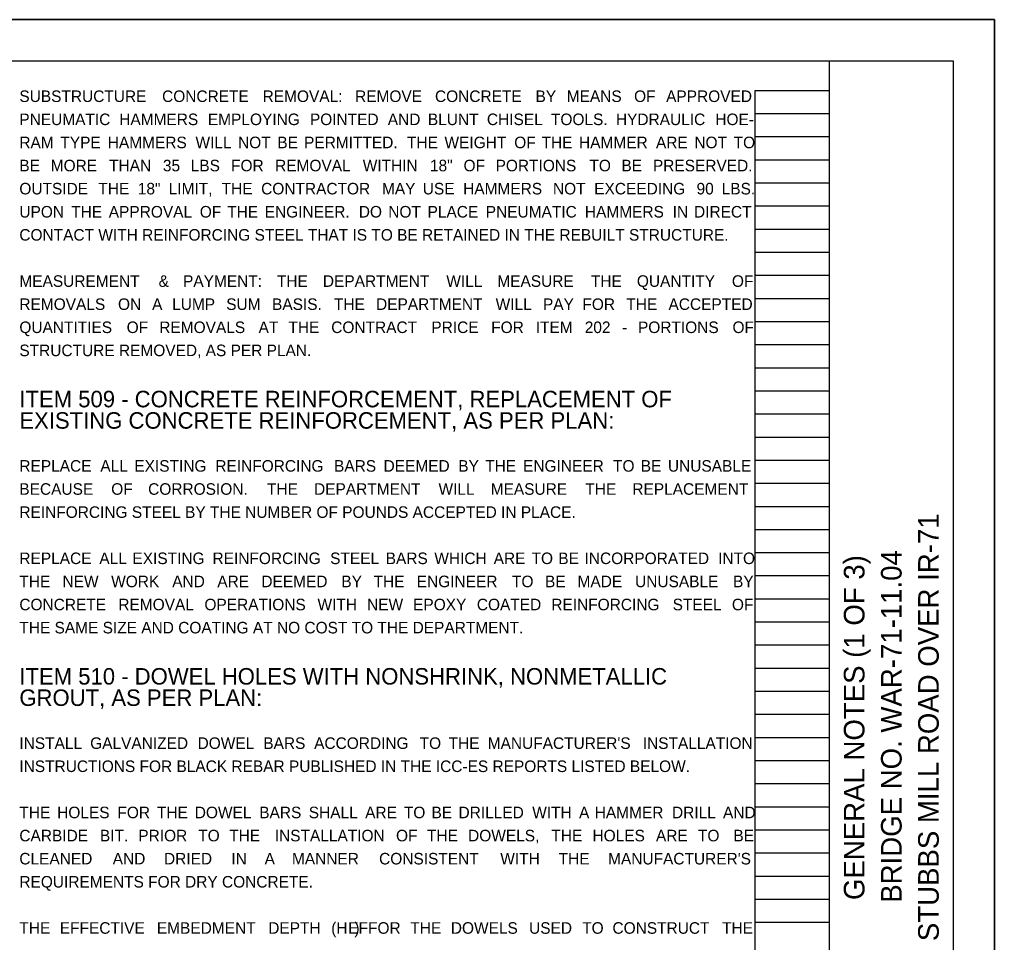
# Model space of a CAD drawing. Extents: x 0 to 34, y 0 to 22.
# Drawn here: x 22.19 to 34, y 10.81 to 22 of the extents above; entities that cross this region are included whole.
import ezdxf

# ---------------------------------------------------------------- set-up
doc = ezdxf.new("R2010")
doc.units = 0
for name, color, linetype in [('BR_P_Gen_Text', 7, 'Continuous'), ('SC_Scratch1', 7, 'Continuous'), ('SH_Border', 7, 'Continuous'), ('SH_Cut_Line', 7, 'Continuous'), ('SH_Data', 7, 'Continuous'), ('SH_Text', 7, 'Continuous')]:
    doc.layers.add(name, color=color, linetype=linetype)

msp = doc.modelspace()

# ---------------------------------------------------------------- linework, layer by layer
at = {"layer": 'SC_Scratch1'}
for p, q in [((31.1, 0.98), (31.1, 21.14)), ((31.1, 21.14), (32, 21.14)), ((32, 0.98), (32, 21.14)), ((31.1, 20.86), (32, 20.86)), ((31.1, 20.58), (32, 20.58)), ((31.1, 20.3), (32, 20.3)), ((31.1, 20.02), (32, 20.02)), ((31.1, 19.74), (32, 19.74)), ((31.1, 19.46), (32, 19.46)), ((31.1, 19.18), (32, 19.18)), ((31.1, 18.9), (32, 18.9)), ((31.1, 18.62), (32, 18.62)), ((31.1, 18.34), (32, 18.34)), ((31.1, 18.06), (32, 18.06)), ((31.1, 17.78), (32, 17.78)), ((31.1, 17.5), (32, 17.5)), ((31.1, 17.22), (32, 17.22)), ((31.1, 16.94), (32, 16.94)), ((31.1, 16.66), (32, 16.66)), ((31.1, 16.38), (32, 16.38)), ((31.1, 16.1), (32, 16.1)), ((31.1, 15.82), (32, 15.82)), ((31.1, 15.54), (32, 15.54)), ((31.1, 15.26), (32, 15.26)), ((31.1, 14.98), (32, 14.98)), ((31.1, 14.7), (32, 14.7)), ((31.1, 14.42), (32, 14.42)), ((31.1, 14.14), (32, 14.14)), ((31.1, 13.86), (32, 13.86)), ((31.1, 13.58), (32, 13.58)), ((31.1, 13.3), (32, 13.3)), ((31.1, 13.02), (32, 13.02)), ((31.1, 12.74), (32, 12.74)), ((31.1, 12.46), (32, 12.46)), ((31.1, 12.18), (32, 12.18)), ((31.1, 11.9), (32, 11.9)), ((31.1, 11.62), (32, 11.62)), ((31.1, 11.34), (32, 11.34)), ((31.1, 11.06), (32, 11.06))]:
    msp.add_line(p, q, dxfattribs=at)
msp.add_lwpolyline([(0, 22), (34, 22), (34, 0), (0, 0)], close=True, dxfattribs=at)
at = {"layer": 'SH_Border'}
msp.add_line((32, 0.5), (32, 21.5), dxfattribs=at)
msp.add_lwpolyline([(1.5, 21.5), (33.5, 21.5), (33.5, 0.5), (1.5, 0.5)], close=True, dxfattribs=at)
at = {"layer": 'SH_Cut_Line'}
msp.add_lwpolyline([(0, 0), (34, 0), (34, 22), (0, 22)], close=True, dxfattribs=at)

# ---------------------------------------------------------------- texts
at = {"layer": 'BR_P_Gen_Text'}
for s, p in [('ITEM 509 - CONCRETE REINFORCEMENT, REPLACEMENT OF ', (22.187, 17.3)), ('EXISTING CONCRETE REINFORCEMENT, AS PER PLAN: ', (22.187, 17.041)), ('ITEM 510 - DOWEL HOLES WITH NONSHRINK, NONMETALLIC ', (22.187, 13.94)), ('GROUT, AS PER PLAN:', (22.187, 13.681))]:
    msp.add_text(s, height=0.2, dxfattribs=at).set_placement(p)
at = {"layer": 'SH_Data'}
for s, p in [('STUBBS MILL ROAD OVER IR-71', (33.325, 10.831)), ('GENERAL NOTES (1 OF 3)', (32.425, 11.329)), ('BRIDGE NO. WAR-71-11.04', (32.875, 11.296))]:
    msp.add_text(s, height=0.25, rotation=90, dxfattribs=at).set_placement(p)
at = {"layer": 'SH_Text'}
for s, p in [('SUBSTRUCTURE ', (22.187, 21)), ('CONCRETE ', (23.916, 21)), ('REMOVAL: ', (25.134, 21)), ('REMOVE ', (26.254, 21)), ('CONCRETE ', (27.222, 21)), ('BY ', (28.44, 21)), ('MEANS ', (28.818, 21)), ('OF ', (29.634, 21)), ('APPROVED ', (30.022, 21)), ('PNEUMATIC ', (22.187, 20.72)), ('HAMMERS ', (23.397, 20.72)), ('EMPLOYING ', (24.471, 20.72)), ('POINTED ', (25.707, 20.72)), ('AND ', (26.65, 20.72)), ('BLUNT ', (27.136, 20.72)), ('CHISEL ', (27.851, 20.72)), ('TOOLS. ', (28.627, 20.72)), ('HYDRAULIC ', (29.414, 20.72)), ('HOE-', (30.618, 20.72)), ('RAM ', (22.187, 20.44)), ('TYPE ', (22.684, 20.44)), ('HAMMERS ', (23.258, 20.44)), ('WILL ', (24.321, 20.44)), ('NOT ', (24.836, 20.44)), ('BE ', (25.312, 20.44)), ('PERMITTED. ', (25.636, 20.44)), ('THE ', (26.883, 20.44)), ('WEIGHT ', (27.337, 20.44)), ('OF ', (28.182, 20.44)), ('THE ', (28.513, 20.44)), ('HAMMER ', (28.967, 20.44)), ('ARE ', (29.899, 20.44)), ('NOT ', (30.364, 20.44)), ('TO ', (30.84, 20.44)), ('BE ', (22.187, 20.16)), ('MORE ', (22.567, 20.16)), ('THAN ', (23.274, 20.16)), ('35 ', (23.926, 20.16)), ('LBS ', (24.263, 20.16)), ('FOR ', (24.752, 20.16)), ('REMOVAL ', (25.285, 20.16)), ('WITHIN ', (26.347, 20.16)), ('18" ', (27.161, 20.16)), ('OF ', (27.568, 20.16)), ('PORTIONS ', (27.956, 20.16)), ('TO ', (29.093, 20.16)), ('BE ', (29.481, 20.16)), ('PRESERVED. ', (29.862, 20.16)), ('OUTSIDE ', (22.187, 19.88)), ('THE ', (23.144, 19.88)), ('18" ', (23.622, 19.88)), ('LIMIT, ', (23.996, 19.88)), ('THE ', (24.638, 19.88)), ('CONTRACTOR ', (25.116, 19.88)), ('MAY ', (26.58, 19.88)), ('USE ', (27.074, 19.88)), ('HAMMERS ', (27.563, 19.88)), ('NOT ', (28.651, 19.88)), ('EXCEEDING ', (29.151, 19.88)), ('90 ', (30.391, 19.88)), ('LBS. ', (30.695, 19.88)), ('UPON ', (22.187, 19.6)), ('THE ', (22.815, 19.6)), ('APPROVAL ', (23.27, 19.6)), ('OF ', (24.373, 19.6)), ('THE ', (24.705, 19.6)), ('ENGINEER. ', (25.159, 19.6)), ('DO ', (26.299, 19.6)), ('NOT ', (26.656, 19.6)), ('PLACE ', (27.132, 19.6)), ('PNEUMATIC ', (27.837, 19.6)), ('HAMMERS ', (29.038, 19.6)), ('IN ', (30.101, 19.6)), ('DIRECT ', (30.36, 19.6)), ('CONTACT WITH REINFORCING STEEL THAT IS TO BE RETAINED IN THE REBUILT STRUCTURE. ', (22.187, 19.32)), ('MEASUREMENT ', (22.187, 18.76)), ('& ', (23.874, 18.76)), ('PAYMENT: ', (24.17, 18.76)), ('THE ', (25.307, 18.76)), ('DEPARTMENT ', (25.864, 18.76)), ('WILL ', (27.359, 18.76)), ('MEASURE ', (27.977, 18.76)), ('THE ', (29.111, 18.76)), ('QUANTITY ', (29.668, 18.76)), ('OF ', (30.819, 18.76)), ('REMOVALS ', (22.187, 18.48)), ('ON ', (23.382, 18.48)), ('A ', (23.795, 18.48)), ('LUMP ', (24.038, 18.48)), ('SUM ', (24.693, 18.48)), ('BASIS. ', (25.248, 18.48)), ('THE ', (25.998, 18.48)), ('DEPARTMENT ', (26.508, 18.48)), ('WILL ', (27.957, 18.48)), ('PAY ', (28.53, 18.48)), ('FOR ', (29.008, 18.48)), ('THE ', (29.54, 18.48)), ('ACCEPTED ', (30.051, 18.48)), ('QUANTITIES ', (22.187, 18.2)), ('OF ', (23.487, 18.2)), ('REMOVALS ', (23.882, 18.2)), ('AT ', (25.085, 18.2)), ('THE ', (25.447, 18.2)), ('CONTRACT ', (25.965, 18.2)), ('PRICE ', (27.178, 18.2)), ('FOR ', (27.903, 18.2)), ('ITEM ', (28.443, 18.2)), ('202 ', (29.036, 18.2)), ('PORTIONS ', (29.681, 18.2)), ('OF ', (30.826, 18.2)), ('- ', (29.489, 18.2)), ('STRUCTURE REMOVED, AS PER PLAN. ', (22.187, 17.92)), ('REPLACE ', (22.187, 16.52)), ('ALL ', (23.168, 16.52)), ('EXISTING ', (23.58, 16.52)), ('REINFORCING ', (24.561, 16.52)), ('BARS ', (25.999, 16.52)), ('DEEMED ', (26.599, 16.52)), ('BY ', (27.504, 16.52)), ('THE ', (27.83, 16.52)), ('ENGINEER ', (28.289, 16.52)), ('TO ', (29.379, 16.52)), ('BE ', (29.715, 16.52)), ('UNUSABLE ', (30.044, 16.52)), ('BECAUSE ', (22.187, 16.24)), ('OF ', (23.3, 16.24)), ('CORROSION. ', (23.747, 16.24)), ('THE ', (25.187, 16.24)), ('DEPARTMENT ', (25.757, 16.24)), ('WILL ', (27.265, 16.24)), ('MEASURE ', (27.897, 16.24)), ('THE ', (29.043, 16.24)), ('REPLACEMENT ', (29.613, 16.24)), ('REINFORCING STEEL BY THE NUMBER OF POUNDS ACCEPTED IN PLACE. ', (22.187, 15.96)), ('REPLACE ', (22.187, 15.4)), ('ALL ', (23.156, 15.4)), ('EXISTING ', (23.557, 15.4)), ('REINFORCING ', (24.527, 15.4)), ('STEEL ', (25.952, 15.4)), ('BARS ', (26.625, 15.4)), ('WHICH ', (27.214, 15.4)), ('ARE ', (27.933, 15.4)), ('TO ', (28.392, 15.4)), ('BE ', (28.716, 15.4)), ('INCORPORATED ', (29.034, 15.4)), ('INTO ', (30.652, 15.4)), ('THE ', (22.187, 15.12)), ('NEW ', (22.71, 15.12)), ('WORK ', (23.299, 15.12)), ('AND ', (24.039, 15.12)), ('ARE ', (24.585, 15.12)), ('DEEMED ', (25.119, 15.12)), ('BY ', (26.088, 15.12)), ('THE ', (26.478, 15.12)), ('ENGINEER ', (27.001, 15.12)), ('TO ', (28.155, 15.12)), ('BE ', (28.555, 15.12)), ('MADE ', (28.949, 15.12)), ('UNUSABLE ', (29.646, 15.12)), ('BY ', (30.833, 15.12)), ('CONCRETE ', (22.187, 14.84)), ('REMOVAL ', (23.386, 14.84)), ('OPERATIONS ', (24.429, 14.84)), ('WITH ', (25.799, 14.84)), ('NEW ', (26.399, 14.84)), ('EPOXY ', (26.957, 14.84)), ('COATED ', (27.729, 14.84)), ('REINFORCING ', (28.631, 14.84)), ('STEEL ', (30.101, 14.84)), ('OF ', (30.819, 14.84)), ('THE SAME SIZE AND COATING AT NO COST TO THE DEPARTMENT.', (22.187, 14.56)), ('INSTALL ', (22.187, 13.16)), ('GALVANIZED ', (23.045, 13.16)), ('DOWEL ', (24.346, 13.16)), ('BARS ', (25.142, 13.16)), ('ACCORDING ', (25.758, 13.16)), ('TO ', (27.036, 13.16)), ('THE ', (27.387, 13.16)), ("MANUFACTURER'S ", (27.861, 13.16)), ('INSTALLATION ', (29.739, 13.16)), ('INSTRUCTIONS FOR BLACK REBAR PUBLISHED IN THE ICC-ES REPORTS LISTED BELOW. ', (22.187, 12.88)), ('THE ', (22.187, 12.32)), ('HOLES ', (22.645, 12.32)), ('FOR ', (23.375, 12.32)), ('THE ', (23.854, 12.32)), ('DOWEL ', (24.312, 12.32)), ('BARS ', (25.093, 12.32)), ('SHALL ', (25.693, 12.32)), ('ARE ', (26.376, 12.32)), ('TO ', (26.845, 12.32)), ('BE ', (27.18, 12.32)), ('DRILLED ', (27.507, 12.32)), ('WITH ', (28.4, 12.32)), ('A ', (28.967, 12.32)), ('HAMMER ', (29.157, 12.32)), ('DRILL ', (30.093, 12.32)), ('AND ', (30.711, 12.32)), ('CARBIDE ', (22.187, 12.04)), ('BIT. ', (23.163, 12.04)), ('PRIOR ', (23.628, 12.04)), ('TO ', (24.354, 12.04)), ('THE  ', (24.729, 12.04)), ('INSTALLATION ', (25.281, 12.04)), ('OF ', (26.75, 12.04)), ('THE ', (27.125, 12.04)), ('DOWELS, ', (27.623, 12.04)), ('THE ', (28.632, 12.04)), ('HOLES ', (29.13, 12.04)), ('ARE ', (29.899, 12.04)), ('TO  ', (30.408, 12.04)), ('BE ', (30.837, 12.04)), ('CLEANED ', (22.187, 11.76)), ('AND ', (23.318, 11.76)), ('DRIED ', (23.939, 11.76)), ('IN ', (24.755, 11.76)), ('A ', (25.158, 11.76)), ('MANNER ', (25.489, 11.76)), ('CONSISTENT ', (26.545, 11.76)), ('WITH ', (28.013, 11.76)), ('THE ', (28.72, 11.76)), ("MANUFACTURER'S ", (29.319, 11.76)), ('REQUIREMENTS FOR DRY CONCRETE. ', (22.187, 11.48)), ('THE ', (22.187, 10.92)), ('EFFECTIVE ', (22.677, 10.92)), ('EMBEDMENT ', (23.853, 10.92)), ('DEPTH ', (25.202, 10.92)), ('(H', (25.965, 10.92)), ('EF', (26.171, 10.92)), (') ', (26.246, 10.92)), ('FOR ', (26.411, 10.92)), ('THE ', (26.923, 10.92)), ('DOWELS ', (27.414, 10.92)), ('USED ', (28.362, 10.92)), ('TO ', (29.005, 10.92)), ('CONSTRUCT ', (29.372, 10.92)), ('THE ', (30.7, 10.92))]:
    msp.add_text(s, height=0.14, dxfattribs=at).set_placement(p)

doc.saveas('drawing.dxf')
